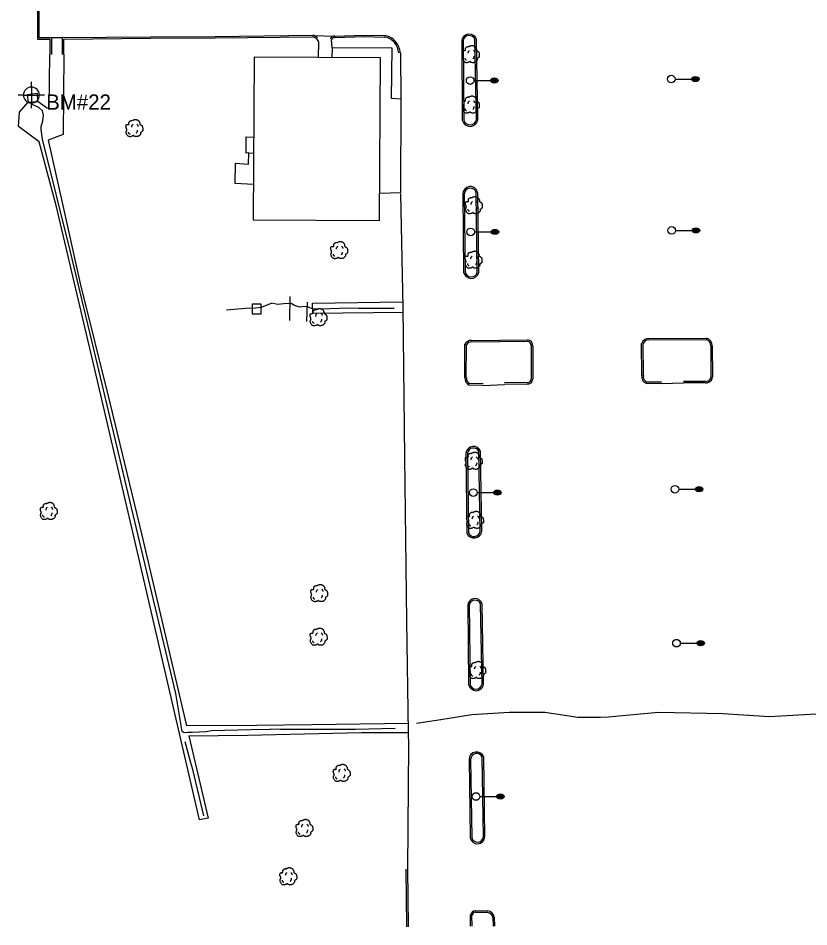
# Model space of a CAD drawing. Extents: x 2145380 to 2156929, y 139568 to 149130.
# Drawn here: x 2148841.9 to 2149152.6, y 142476.1 to 142833.1 of the extents above; entities that cross this region are included whole.
import ezdxf

# ---------------------------------------------------------------- set-up
doc = ezdxf.new("R2010")
doc.units = 0
for name, color, linetype in [('SURV_Benchmark', 7, 'Continuous'), ('SURV_Text', 7, 'Continuous'), ('TOPO_Asphalt', 7, 'Continuous'), ('TOPO_Building', 7, 'Continuous'), ('TOPO_Concrete', 7, 'Continuous'), ('TOPO_Curb Back', 7, 'Continuous'), ('TOPO_DRAIN_Headwall', 7, 'Continuous'), ('TOPO_Flowline', 7, 'Continuous'), ('TOPO_Light Pole', 7, 'Continuous'), ('TOPO_Pipeline', 7, 'Continuous'), ('TOPO_Sidewalk', 7, 'Continuous'), ('TOPO_Tree', 7, 'Continuous')]:
    doc.layers.add(name, color=color, linetype=linetype)

# ---------------------------------------------------------------- blocks, each defined once
blk = doc.blocks.new('LP')
at = {"layer": 'TOPO_Light Pole'}
blk.add_line((3.81, 0), (20.32, 0), dxfattribs=at)
for points in [[(20.32, 0), (27.94, 0)], [(20.32, 0), (23.5, 0)], [(20.83, 1.27), (27.43, 1.27)], [(20.83, 1.27), (23.5, 1.27)], [(23.71, 1.27), (27.43, 1.27)], [(23.71, 0), (27.94, 0)], [(20.83, -1.27), (27.43, -1.27)], [(20.83, -1.27), (23.5, -1.27)], [(23.71, -1.27), (27.43, -1.27)]]:
    blk.add_lwpolyline(points, dxfattribs=at)
blk.add_circle((0, 0), 3.81, dxfattribs=at)
blk.add_ellipse((24.13, 0), major_axis=(3.81, 0), ratio=0.666667, dxfattribs=at)
blk = doc.blocks.new('TREE')
at = {"layer": 'TOPO_Tree'}
for points in [[(-14.1, -0.4), (-14.2, 0.5), (-14.4, 1.4), (-14.6, 2.3), (-14.8, 3.2), (-15.5, 4), (-15.7, 4.9), (-15.8, 5.6), (-15.7, 6.3), (-15.7, 7), (-15.6, 7.9), (-15.7, 8.8), (-15.1, 9.7), (-14.6, 10.4), (-13.8, 10.5), (-13, 10.7), (-12.2, 11), (-11.1, 10), (-10.4, 10.7), (-9.4, 11.7), (-10.3, 13.3), (-9.8, 14.4), (-9.6, 15.1), (-9.3, 15.9), (-8.8, 16.5), (-8.2, 17.3), (-7.5, 17.7), (-6.7, 18.1), (-6.1, 18.4), (-5.6, 18.6), (-5.1, 18.7), (-4.5, 18.7), (-4, 18.5), (-3.5, 18.1)], [(-3.5, 17.6), (-3.1, 18.3), (-2.6, 18.8), (-1.9, 19.2), (-1, 19.7), (-0.2, 20), (0.7, 20.2), (1.6, 20.5), (2.5, 20.8), (3.4, 20.8), (4.1, 20.7), (4.8, 20.5), (5.5, 20.2), (6.4, 19.9), (7.3, 19.7), (8.2, 19.2), (9.4, 18.4), (10, 17.2), (10.8, 16), (11.2, 15.3), (11.6, 14.6), (11.9, 13.9), (12.2, 13.1), (11.4, 12), (11.9, 11.2), (12, 11), (12.2, 10.9), (12.4, 10.7), (12.9, 10.4), (13.5, 10), (14, 9.7), (14.7, 9.2), (15.4, 8.7), (16.1, 8.1), (16.7, 7.5), (16.9, 6.7), (17.1, 6), (17.6, 4.4), (17.7, 2.8), (17.7, 1.2), (17.7, -0.2), (17.8, -2.2), (16.6, -3), (15.5, -3.8), (14.3, -4.6), (13.2, -5.3)], [(13.2, -5.3), (13.3, -5.8), (13.4, -6.3), (13.4, -6.7), (13.8, -8.5), (12.2, -10), (10.8, -11.5), (10, -12.3), (9.1, -12.8), (8.2, -13.1), (6, -13.8), (3.3, -13.6), (1.3, -13.1), (0.5, -12.9), (-0.1, -11.4), (-0.8, -11.5), (-2, -11.6), (-3.3, -12.8), (-4.5, -13.1), (-6.1, -13.5), (-7.8, -14), (-9.3, -13.6), (-11.4, -13.1), (-12.8, -11.4), (-14.1, -9.4), (-15.3, -7.3), (-15.6, -5.1), (-15.1, -3), (-14.9, -1.9), (-13.9, -0.8), (-13.5, 0.1)], [(-4.2, 5.1), (-4.5, 6.1), (-4.3, 7.2), (-3.8, 8.2), (-3.3, 9.3), (-2.7, 10.3), (-1.6, 11)], [(5.9, 11.2), (6.5, 10.7), (7, 10.2), (7.4, 9.5), (7.9, 8.6), (8.3, 7.6), (8.5, 6.6)], [(-11.4, -4.5), (-11.5, -5.4), (-11, -6.3), (-10.1, -7.2), (-9.3, -8), (-8.5, -8.3), (-7.7, -8.1)], [(4.8, -6.3), (5.7, -5.7), (6.3, -4.9), (6.8, -3.9), (7.4, -2.8), (7.6, -1.7), (7.5, -0.6)]]:
    blk.add_open_spline(points, degree=3, dxfattribs=at)
blk = doc.blocks.new('BM')
at = {"layer": 'SURV_Benchmark'}
for p, q in [((0, 2.49), (0, 4.15)), ((-2.49, 0), (-4.16, 0)), ((4.16, 0), (2.49, 0)), ((0, -4.16), (0, -2.49))]:
    blk.add_line(p, q, dxfattribs=at)
for points in [[(-2.5, 0), (-2.49, 0), (0, 0), (0, -2.49), (0, -2.49)], [(-2.5, 0), (-2.49, 0), (0, 0), (0, -2.49), (0, -2.49)], [(0, 2.49), (0, 2.49), (0, 0), (2.49, 0), (2.49, 0), (2.49, 0)], [(0, 2.49), (0, 2.49), (0, 0), (2.49, 0), (2.49, 0), (2.49, 0), (2.49, 0)]]:
    blk.add_lwpolyline(points, dxfattribs=at)
for start, end in [(90.0638, 180.0068), (0.0638, 90.0068), (0.0638, 90.0068), (180.0638, 270.0068), (180.0638, 270.0068), (269.9472, 359.9927)]:
    blk.add_arc((0, 0), 2.5, start, end, dxfattribs=at)

msp = doc.modelspace()

# ---------------------------------------------------------------- linework, layer by layer
at = {"layer": 'TOPO_Asphalt'}
for p, q in [((2148854.91, 142825.5), (2148859.39, 142825.54)), ((2148957.98, 142826.36), (2148966.39, 142826.14)), ((2148992.07, 142819.57), (2148992.3, 142801.27)), ((2149024.55, 142688.82), (2149033.01, 142689.22)), ((2149094.65, 142689.6), (2149103.32, 142689.81))]:
    msp.add_line(p, q, dxfattribs=at)
msp.add_lwpolyline([(2148994.97, 142498.82), (2148995.35, 142547.45), (2148995.28, 142552.46), (2148994.65, 142596.26), (2148993.83, 142660.68), (2148993.19, 142719.46), (2148992.3, 142764.15)], dxfattribs=at)
at = {"layer": 'TOPO_Building'}
msp.add_lwpolyline([(2148934.61, 142817.78), (2148934.24, 142753.87), (2148983.91, 142753.59), (2148984.27, 142817.5)], close=True, dxfattribs=at)
at = {"layer": 'TOPO_Concrete'}
msp.add_line((2148854.05, 142797.42), (2148854.37, 142818.9), dxfattribs=at)
for points in [[(2148983.97, 142764.42), (2148992.29, 142764.62), (2148992.4, 142801.26), (2148988.56, 142801.56), (2148988.88, 142821.35), (2148965.29, 142821.54), (2148965.12, 142817.61)], [(2148859.83, 142818.84), (2148859.54, 142787.46), (2148853.65, 142785.21), (2148859.41, 142759.5), (2148866.28, 142728.91), (2148877.87, 142682.05), (2148890.43, 142629.95), (2148905.18, 142567.34), (2148908.05, 142555.05)], [(2148908.96, 142551.16), (2148916.53, 142518.79), (2148913.19, 142518.18), (2148887.51, 142628.98), (2148872.03, 142695.1), (2148856.96, 142759.03), (2148850.16, 142784.6), (2148842.05, 142790.64), (2148842.45, 142796.25)], [(2148934.32, 142767.73), (2148927.19, 142768.14), (2148927.26, 142776.19), (2148932.37, 142775.8), (2148932.57, 142780.17), (2148934.39, 142780.11)], [(2148937.4, 142720.82), (2148933.82, 142720.81), (2148933.83, 142717), (2148937.41, 142717.01), (2148937.4, 142720.82)], [(2148993.21, 142717.55), (2148957.68, 142717.12), (2148957.56, 142721.12), (2148993.02, 142721.68)], [(2148995.23, 142555.93), (2148957.47, 142555.51), (2148935.59, 142555.19), (2148908.05, 142555.05)], [(2148908.96, 142551.16), (2148932, 142551.46), (2148976.8, 142552.4), (2148995.28, 142552.46)]]:
    msp.add_lwpolyline(points, dxfattribs=at)
at = {"layer": 'TOPO_Curb Back'}
for p, q in [((2149016.6, 142764.01), (2149016.9, 142733.39)), ((2149017.2, 142764.01), (2149017.5, 142733.44)), ((2149017.2, 142764.01), (2149017.2, 142764.01)), ((2149022.28, 142733.3), (2149021.89, 142764.49)), ((2149022.88, 142733.23), (2149022.49, 142764.56)), ((2148994.62, 142476.09), (2148994.37, 142498.81)), ((2148995.22, 142476.1), (2148994.97, 142498.82))]:
    msp.add_line(p, q, dxfattribs=at)
for points in [[(2148855.65, 142909.85), (2148848.39, 142909.64), (2148848.94, 142887.77), (2148849.27, 142847.9), (2148849.42, 142824.91), (2148854.32, 142824.9), (2148854.37, 142818.9)], [(2148855.65, 142909.25), (2148849.01, 142909.05), (2148849.54, 142887.78), (2148849.87, 142847.91), (2148850.02, 142825.51), (2148854.91, 142825.5), (2148854.97, 142818.9)], [(2148859.23, 142818.84), (2148859.26, 142825.54), (2148893.86, 142825.85), (2148919.24, 142825.97), (2148957.66, 142826.47)], [(2148859.83, 142818.84), (2148859.86, 142824.94), (2148893.87, 142825.25), (2148919.25, 142825.37), (2148957.57, 142825.86)], [(2148966.37, 142825.54), (2148977.87, 142825.93), (2148985.71, 142825.73)], [(2148966.38, 142826.14), (2148977.87, 142826.53), (2148985.74, 142826.33)], [(2149016.19, 142824.53), (2149016.41, 142793.02)], [(2149016.79, 142824.53), (2149017.01, 142793.1)], [(2149021.94, 142793.2), (2149021.41, 142824.68)], [(2149022.54, 142793.14), (2149022, 142824.77)], [(2149020.09, 142705.93), (2149042.01, 142706.19)], [(2149020.1, 142706.53), (2149042.05, 142706.79)], [(2149089.65, 142706.69), (2149112.27, 142706.84)], [(2149089.66, 142707.29), (2149112.35, 142707.44)], [(2149017.4, 142691.89), (2149017.44, 142705.01)], [(2149018, 142691.88), (2149018.04, 142704.86)], [(2149043.53, 142704.27), (2149043.53, 142691.38)], [(2149044.13, 142704.25), (2149044.13, 142691.36)], [(2149087.04, 142692.8), (2149086.92, 142705.37)], [(2149087.64, 142692.72), (2149087.52, 142705.27)], [(2149114.06, 142704.39), (2149114.16, 142692.24)], [(2149114.66, 142704.39), (2149114.76, 142692.22)], [(2149024.55, 142688.82), (2149019.16, 142688.98)], [(2149024.56, 142689.42), (2149019.31, 142689.58)], [(2149041.94, 142689.96), (2149033, 142689.82)], [(2149041.93, 142689.36), (2149033.01, 142689.22)], [(2149094.65, 142689.6), (2149088.83, 142689.56)], [(2149094.65, 142690.2), (2149088.93, 142690.16)], [(2149111.97, 142690.39), (2149103.32, 142690.41)], [(2149111.99, 142689.79), (2149103.32, 142689.81)], [(2149023.49, 142631.56), (2149022.96, 142662.83)], [(2149024.09, 142631.51), (2149023.55, 142662.95)], [(2149017.86, 142662.2), (2149018.23, 142630.74)], [(2149018.46, 142662.21), (2149018.83, 142630.88)], [(2149018.56, 142602.57), (2149018.85, 142571.4)], [(2149019.16, 142602.58), (2149019.45, 142571.45)], [(2149024.18, 142571.48), (2149023.6, 142602.78)], [(2149024.78, 142571.44), (2149024.2, 142602.86)], [(2149019.09, 142541.89), (2149019.53, 142511.13)], [(2149019.69, 142541.9), (2149020.13, 142511.19)], [(2149024.74, 142511.45), (2149024.25, 142542.72)], [(2149025.34, 142511.43), (2149024.85, 142542.84)], [(2149019.67, 142476.31), (2149019.59, 142480.73)], [(2149020.27, 142476.32), (2149020.19, 142480.65)], [(2149021.54, 142482.4), (2149026.42, 142482.35)], [(2149021.57, 142481.8), (2149026.37, 142481.75)], [(2149028.41, 142479.79), (2149028.51, 142476.39)], [(2149029.01, 142479.86), (2149029.11, 142476.4)]]:
    msp.add_lwpolyline(points, dxfattribs=at)
for centre, radius, start, end in [((2149019.12, 142823.93), 3, 16.2908, 167.2019), ((2148956.2, 142821.69), 4.39, 48.3772, 71.787), ((2148956.2, 142821.69), 4.99, 48.3767, 72.9726), ((2148966.29, 142824.1), 2.04, 87.6695, 149.4811), ((2148966.29, 142824.1), 1.44, 86.8548, 149.4882), ((2148985.16, 142819.9), 5.86, 38.5222, 84.6393), ((2148985.16, 142819.9), 6.46, 38.5472, 84.8232), ((2148983.54, 142818.52), 7.99, 7.0443, 39.0437), ((2148983.54, 142818.52), 8.59, 7.044, 39.028), ((2149019.12, 142823.93), 2.4, 18.1092, 167.2032), ((2149019.46, 142793.78), 3.15, 193.968, 348.2967), ((2149019.46, 142793.78), 2.55, 195.4916, 346.8737), ((2149019.57, 142763.99), 2.97, 10.9302, 179.7598), ((2149019.57, 142763.99), 2.37, 12.1535, 179.7012), ((2149019.91, 142733.91), 3.05, 189.8022, 347.2654), ((2149019.91, 142733.91), 2.45, 190.8757, 345.7007), ((2149019.95, 142703.69), 2.84, 87.0516, 152.2924), ((2149019.95, 142703.69), 2.24, 86.5952, 148.7381), ((2149041.72, 142704.39), 1.82, 356.0146, 80.6836), ((2149041.72, 142704.39), 2.42, 356.5447, 82.0142), ((2149089.55, 142704.54), 2.75, 87.6461, 162.5231), ((2149089.55, 142704.54), 2.15, 87.2863, 160.143), ((2149111.51, 142704.41), 2.55, 359.6374, 72.8259), ((2149111.51, 142704.41), 3.15, 359.7223, 74.6012), ((2149020.57, 142691.81), 3.16, 178.6214, 243.5111), ((2149020.57, 142691.81), 2.56, 178.4893, 240.7083), ((2149042.01, 142691.49), 2.13, 267.7878, 356.6797), ((2149042.01, 142691.49), 1.53, 267.2198, 356.0825), ((2149089.66, 142692.14), 2.7, 165.7814, 252.263), ((2149089.66, 142692.14), 2.1, 163.7942, 249.8123), ((2149112.22, 142692.42), 1.95, 294.4926, 354.8809), ((2149112.22, 142692.42), 2.55, 294.4894, 355.5865), ((2149111.83, 142693.29), 2.9, 272.8815, 294.4742), ((2149111.83, 142693.29), 3.5, 272.6149, 294.4685), ((2149020.79, 142661.92), 2.95, 20.4784, 173.9147), ((2149020.79, 142661.92), 2.35, 22.8583, 173.9127), ((2149021.05, 142631.96), 3.07, 203.3961, 351.6218), ((2149021.05, 142631.96), 2.47, 206.0444, 350.546), ((2149021.4, 142602.17), 2.88, 13.783, 171.0221), ((2149021.4, 142602.17), 2.28, 15.3682, 171.0233), ((2149021.81, 142571.88), 3, 189.1704, 351.5647), ((2149021.81, 142571.88), 2.4, 190.189, 350.4421), ((2149022.06, 142541.82), 2.97, 19.9582, 178.4919), ((2149022.06, 142541.82), 2.37, 22.2634, 178.4911), ((2149022.41, 142511.69), 2.94, 190.9965, 354.9518), ((2149022.41, 142511.69), 2.34, 192.2318, 354.2322), ((2149021.75, 142480.17), 2.23, 95.4209, 165.6551), ((2149021.75, 142480.17), 1.63, 96.4245, 163.0184), ((2149025.98, 142479.31), 2.47, 11.2133, 81.0043), ((2149025.98, 142479.31), 3.07, 10.2325, 81.8788)]:
    msp.add_arc(centre, radius, start, end, dxfattribs=at)
at = {"layer": 'TOPO_DRAIN_Headwall'}
for points in [[(2148849.64, 142800.43), (2148849.42, 142803.49), (2148845.45, 142803.07), (2148845.73, 142800.08)], [(2148842.45, 142796.25), (2148845.73, 142800.08), (2148849.74, 142800.47), (2148853.41, 142797.82)]]:
    msp.add_lwpolyline(points, dxfattribs=at)
at = {"layer": 'TOPO_Flowline'}
for points in [[(2148990.03, 142553.98), (2148974.46, 142553.57), (2148954.93, 142553.67), (2148953.42, 142553.65), (2148945.79, 142553.64), (2148944.93, 142553.59), (2148941.17, 142553.74), (2148940.83, 142553.67), (2148933.45, 142553.46), (2148917.85, 142553.1), (2148915.69, 142552.77), (2148910.25, 142552.5), (2148908.59, 142552.43), (2148907.14, 142552.36), (2148906.3, 142552.85), (2148903.84, 142567.79), (2148887.06, 142638.17), (2148871.62, 142703.14), (2148862.27, 142741.82), (2148851.45, 142785.64), (2148850.86, 142789.42), (2148850.88, 142790.57), (2148851.56, 142792.78), (2148851.88, 142795.07), (2148851.39, 142796.7), (2148850.04, 142798.04), (2148847.3, 142799.21)], [(2148989.63, 142719.03), (2148975.63, 142719), (2148971.91, 142719.21), (2148964.39, 142718.98), (2148957.66, 142718.85), (2148955.91, 142719.62), (2148954.13, 142719.89), (2148952.53, 142719.57), (2148950.46, 142720.27), (2148949.11, 142721.01), (2148946.31, 142720.92), (2148943.83, 142720.64), (2148941.56, 142721.11), (2148937.41, 142719.45), (2148935.18, 142719.2), (2148931.27, 142719.01), (2148923.73, 142718.39)], [(2149213.88, 142559.83), (2149188.75, 142561.25), (2149174.72, 142560.75), (2149157.74, 142559.81), (2149137.16, 142558.6), (2149118.88, 142559.74), (2149093.58, 142560.28), (2149073.81, 142558.42), (2149070.74, 142558.36), (2149061.78, 142558.4), (2149048.83, 142560.27), (2149034.87, 142560.36), (2149020.17, 142559.37), (2149008, 142557.41), (2148998.46, 142556.05)], [(2148914.89, 142519.7), (2148910.55, 142537.86), (2148909.73, 142540.5), (2148907.48, 142548.8)]]:
    msp.add_lwpolyline(points, dxfattribs=at)
at = {"layer": 'TOPO_Pipeline'}
for p, q in [((2148948.7, 142723.76), (2148948.5, 142714.37)), ((2148955.39, 142721.51), (2148955.13, 142713.91))]:
    msp.add_line(p, q, dxfattribs=at)
at = {"layer": 'TOPO_Sidewalk'}
msp.add_line((2148965.29, 142821.54), (2148965.05, 142824.83), dxfattribs=at)
for points in [[(2148959.14, 142824.98), (2148959.89, 142823.89), (2148959.81, 142817.64)], [(2148932.57, 142780.17), (2148931.42, 142780.12), (2148931.52, 142786.55), (2148934.43, 142786.43)]]:
    msp.add_lwpolyline(points, dxfattribs=at)

# ---------------------------------------------------------------- block references
at = {"layer": 'SURV_Benchmark', "xscale": 1.25, "yscale": 1.25}
msp.add_blockref('BM', (2148847.06, 142802.93), dxfattribs=at)
at = {"layer": 'TOPO_Light Pole', "xscale": 0.39370000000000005, "yscale": 0.3937000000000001}
for p in [(2149019.51, 142808.65), (2149098.55, 142809.2), (2149019.72, 142749.15), (2149098.73, 142749.75), (2149099.97, 142648.05), (2149020.75, 142646.71), (2149100.61, 142587.56), (2149021.86, 142527.3)]:
    msp.add_blockref('LP', p, dxfattribs=at)
at = {"layer": 'TOPO_Tree', "xscale": 0.19685000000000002, "yscale": 0.19685000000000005}
for p in [(2149019.62, 142818.35), (2149019.62, 142798.52), (2148887.34, 142789.28), (2149020.78, 142758.99), (2148967.84, 142741.34), (2149020.66, 142737.57), (2148959.72, 142714.97), (2149020.72, 142658.55), (2148853.7, 142638.83), (2149021.23, 142635.35), (2148959.99, 142606.56), (2148959.77, 142589.42), (2149022.12, 142576.33), (2148968.83, 142535.91), (2148954.18, 142514.26), (2148947.85, 142495.28)]:
    msp.add_blockref('TREE', p, dxfattribs=at)

# ---------------------------------------------------------------- texts
at = {"layer": 'SURV_Text'}
msp.add_text('BM#22', height=6, dxfattribs=at).set_placement((2148852.88, 142797.18))

doc.saveas('drawing.dxf')
